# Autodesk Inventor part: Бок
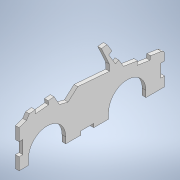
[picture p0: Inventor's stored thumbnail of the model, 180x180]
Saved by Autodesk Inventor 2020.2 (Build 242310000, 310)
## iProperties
Created: 2020-04
Part Number: Бок
Material: Типовые
Document SubType Name: Modeling
Designer: Алексей
Density: 1 g/cm^3
Appearance: По умолчанию
Author: Алексей
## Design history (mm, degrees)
sketch "Эскиз1"
  geometry: L1 (0, 0)-(0, -10); L2 (0, -50)-(0, -96); L3 (0, -136)-(0, -156); L4 (0, -156)-(34, -156); L5 (34, -156)-(41, -112); L6 (41, -112)-(70, -94.306); L7 (70, -94.306)-(69.328, -88.306); L8 (69.328, -88.306)-(50.736, -96.735); L9 (39.88, -43.2)-(50, -37.5); L10 (50, -37.5)-(47.5, -11); L11 (47.5, -11)-(42.718, -7.895); L12 (42.718, -7.895)-(40, 0); L13 (40, 0)-(0, 0); L14 (6.625, -50)-(0, -50); L15 (6.625, -96)-(0, -96); L16 (6.625, -10)-(0, -10); L17 (6.625, -136)-(0, -136); L18 (50.736, -96.735)-(43.938, -96.9); L19 (43.938, -96.9)-(46.68, -62.9); L20 (39.88, -43.2)-(37.58, -52.5); L21 (37.58, -52.5)-(46.68, -62.9); A1 r 20 centre (6.625, -30) between (6.625, -50) and (6.625, -10); A2 r 20 centre (6.625, -116) between (6.625, -136) and (6.625, -96)
  constraints: 42 end point, 5 perpendicular, 4 point on circle, 4 tangent, 2 centre point, 2 vertical, 1 collinear, 1 horizontal, 1 point on line, 1 vertical alignment
  dimensions: "d35" = 40 diameter of A1; "d37" = 40 diameter of A2; "d39" = 6.625 distance from line of L1 A1.centre; "d40" = 30 distance from line of L13 A1.centre; "d41" = 40 distance from line of L4 A2.centre; "d42" = 156 distance of L3.end L1.start; "d43" = 34 distance of L3.end L4.end; "d44" = 40 distance of L12.end L1.start; "d46" = 41 horizontal distance of L3.end L5.end; "d47" = 44 distance from line of L4 L5.end; "d48" = 70 distance from line of L3 L6.end; "d49" = 50 horizontal distance of L1.start L9.end; "d50" = 37.5 vertical distance of L1.start L9.end; "d51" = 5.7 vertical distance of L9.start L9.end; "d52" = 7.5 horizontal distance of L12.end L10.end; "d53" = 11 vertical distance of L12.end L10.end; "d54" = 142 deg angle of L12 L11; "d55" = 109 deg angle of L13 L12; "d56" = 114 deg angle of L10 L9; "d57" = 9.3 vertical distance of L20.end L9.start; "d58" = 9.1 horizontal distance of L19.end L20.end; "d59" = 10.4 vertical distance of L19.end L20.end; "d60" = 34 vertical distance of L18.end L19.end; "d62" = 6.8 distance of L8.end L18.end; "d63" = 115 deg angle of L6 L7; "d64" = 6 vertical distance of L6.end L7.end; "d65" = 72 deg angle of L8 L7; "d66" = 85 deg angle of L18 L7; "d67" = 11 deg angle of L19 L7; "d68" = 1 deg angle of L7 L10
extrude "Выдавливание1" new body sketch "Эскиз1" distance "d69" = 4; taper "d70" = 0 deg
sketch "Эскиз2"
  geometry: L1 (66, 4)-(80, 4); L2 (80, 4)-(80, 0); L3 (80, 0)-(66, 0); L4 (66, 0)-(66, 4); L5 (50, 0)-(96, 0) reference; L6 (0, 40)-(0, 0) reference; L7 (0, 27)-(4, 27); L8 (4, 27)-(4, 13); L9 (4, 13)-(0, 13); L10 (0, 13)-(0, 27); L11 (156, 24)-(152, 24); L12 (152, 24)-(152, 10); L13 (152, 10)-(156, 10); L14 (156, 10)-(156, 24); L15 (156, 34)-(112, 41) reference; L16 (127.087, 38.6)-(140.913, 36.4); L17 (140.913, 36.4)-(140.285, 32.45); L18 (140.285, 32.45)-(126.458, 34.649); L19 (126.458, 34.649)-(127.087, 38.6); L20 (37.5, 50)-(11, 47.5) reference; L21 (17.281, 48.093)-(31.219, 49.407); L22 (31.219, 49.407)-(31.595, 45.425); L23 (31.595, 45.425)-(17.657, 44.11); L24 (17.657, 44.11)-(17.281, 48.093); L25 (112, 41)-(94.306, 70) reference; L26 (106.799, 49.524)-(99.507, 61.476); L27 (99.507, 61.476)-(96.092, 59.392); L28 (96.092, 59.392)-(103.384, 47.441); L29 (103.384, 47.441)-(106.799, 49.524); L30 (156, 0)-(156, 34) reference; 10 further points
  constraints: 48 end point, 12 midpoint, 12 parallel, 6 perpendicular, 4 collinear, 4 point on line, 3 horizontal
  dimensions: "d71" = 14 distance of L2.end L3.end; "d72" = 4 distance of L1.end L2.end; "d73" = 4 distance of L8.end L9.end; "d74" = 14 distance of L7.end L8.end; "d75" = 4 distance of L13.end L12.end; "d76" = 14 distance of L12.end L11.end; "d77" = 14 distance of L17.end L18.end; "d78" = 4 distance of L16.end L17.end; "d79" = 14 distance of L22.end L23.end; "d80" = 4 distance of L21.end L22.end; "d81" = 14 distance of L28.end L27.end; "d82" = 4 distance of L27.end L26.end
extrude "Выдавливание2" cut sketch "Эскиз2" extent not by distance; stored distance "d83" = 0; taper "d84" = 0 deg
fillet "Сопряжение1" dims "d85" = 4
sketch "Эскиз3"
  geometry: L1 (-62.9, 46.68)-(-96.9, 43.938) reference; L2 (-96.9, 43.938)-(-96.9, 28.562) reference; L3 (-96.9, 28.562)-(-83.226, 14.657) reference; L4 (-83.226, 14.657)-(-67.471, 14.657) reference; L5 (-67.471, 14.657)-(-62.9, 19.152) reference; L6 (-62.9, 19.152)-(-62.9, 46.68) reference; L7 (-52.5, 37.58)-(-43.2, 39.88) reference; L8 (-62.9, 19.152)-(-52.5, 37.58); L9 (-62.9, 46.68)-(-52.5, 37.58) reference; L10 (-52.5, 37.58)-(-62.9, 46.68); L11 (-62.9, 46.68)-(-62.9, 19.152); 2 further points
  constraints: 6 end point, 2 collinear
extrude "Выдавливание3" cut sketch "Эскиз3" extent not by distance; stored distance "d86" = 0; taper "d87" = 0 deg
node "Твердое тело1"
node "Ссылка1"
other parameters: "d34" = 156
